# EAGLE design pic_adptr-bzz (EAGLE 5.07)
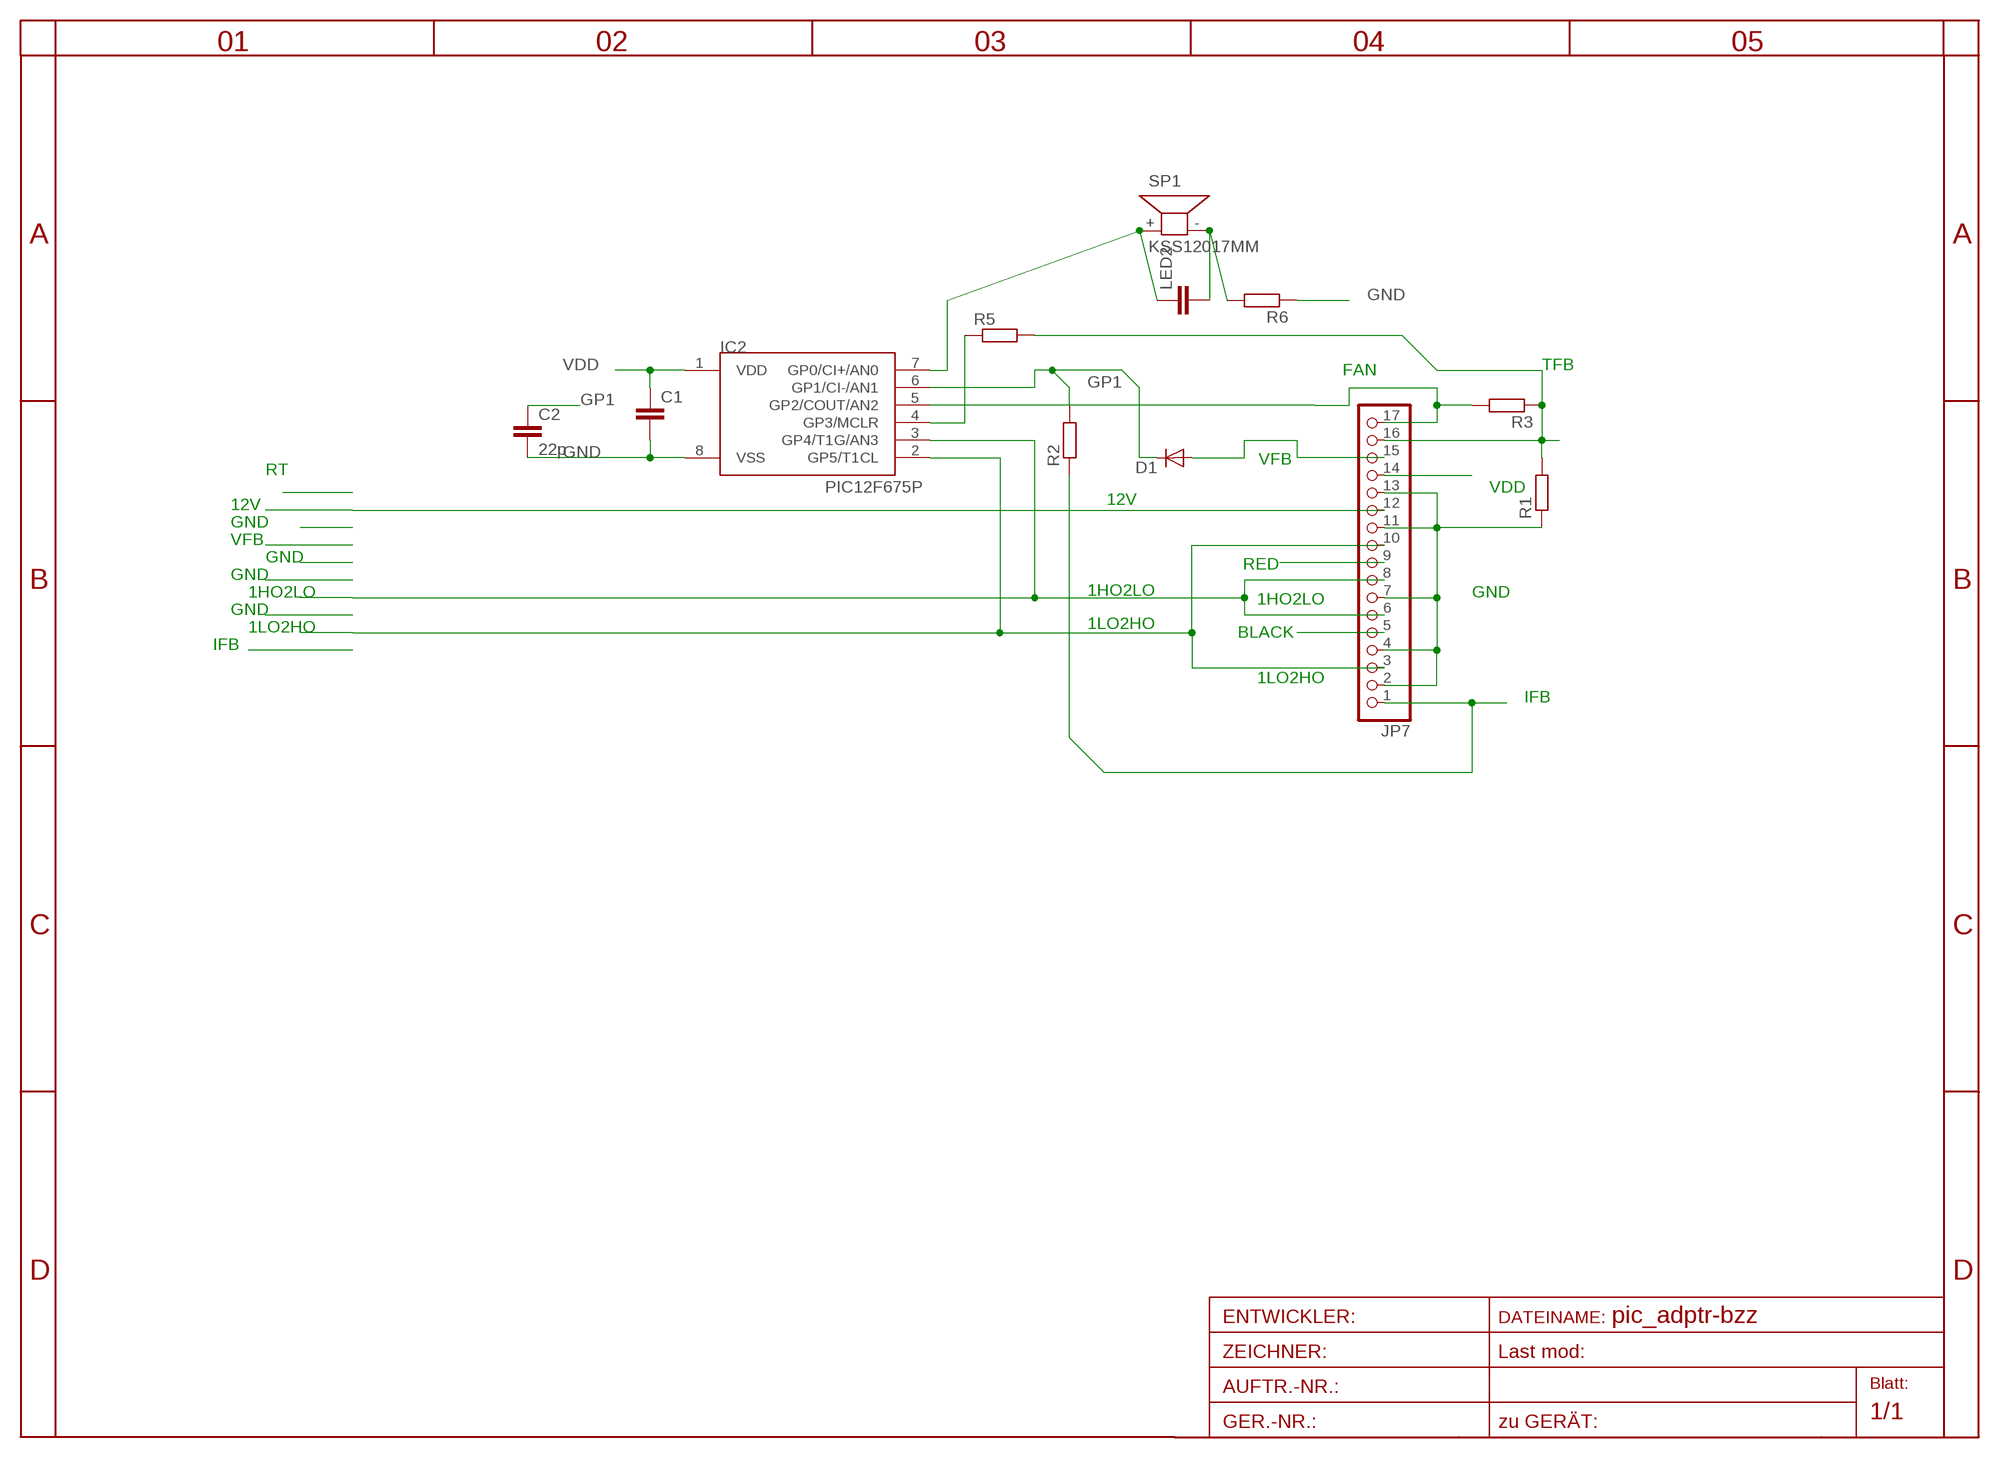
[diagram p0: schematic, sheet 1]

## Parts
C1  C-EUC1206  [C1206]
C2  22p  C-EUC0805  [C0805]
D1  DIODE-MINIMELF  [MINIMELF]
IC2  PIC12F675P  [DIL8]
JP7  PINHD-1X17  [1X17]
LED2  C-EUC1206K  [C1206K]
R1  R-EU_R1206  [R1206]
R2  R-EU_R0805  [R0805]
R3  R-EU_R0805  [R0805]
R5  R-EU_R0805  [R0805]
R6  R-EU_R0805  [R0805]
SP1  KSS12017MM  [KSS1202]

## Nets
1HO2LO: IC2.3(GP4/T1G/AN3) JP7.6 JP7.8
1LO2HO: IC2.2(GP5/T1CL) JP7.3 JP7.10
12V: JP7.12
BLACK: JP7.5
FAN: IC2.5(GP2/COUT/AN2) JP7.17 R3.2
GND: C1.2 C2.2 IC2.8(VSS) JP7.2 JP7.4 JP7.7 JP7.11 JP7.13 R1.1 R6.1
GP1: C2.1 D1.C IC2.6(GP1/CI-/AN1) R2.2
IFB: JP7.1 R2.1
N$3: IC2.4(GP3/MCLR) R5.1
N$4: IC2.7(GP0/CI+/AN0) LED2.1 SP1.+
N$5: LED2.2 R6.2 SP1.-
RED: JP7.9
TFB: JP7.16 R1.2 R3.1 R5.2
VDD: C1.1 IC2.1(VDD) JP7.14
VFB: D1.A JP7.15

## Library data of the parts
C1 C2 = rcl:C-EU: CAPACITOR, European symbol
D1 = diode:DIODE-: DIODE
IC2 = microchip-5:PIC12F6*: uPC nW 1k Program Flash memory 2x Timer Comparator 10b A/D converter/ 4xIN
JP7 = pinhead:PINHD-1X17: PIN HEADER
LED2 = rcl-2:C-EU: CAPACITOR, European symbol
R1-R3 R5 R6 = rcl:R-EU_: RESISTOR, European symbol
SP1 = buzzer:KSS1201: SPEAKER

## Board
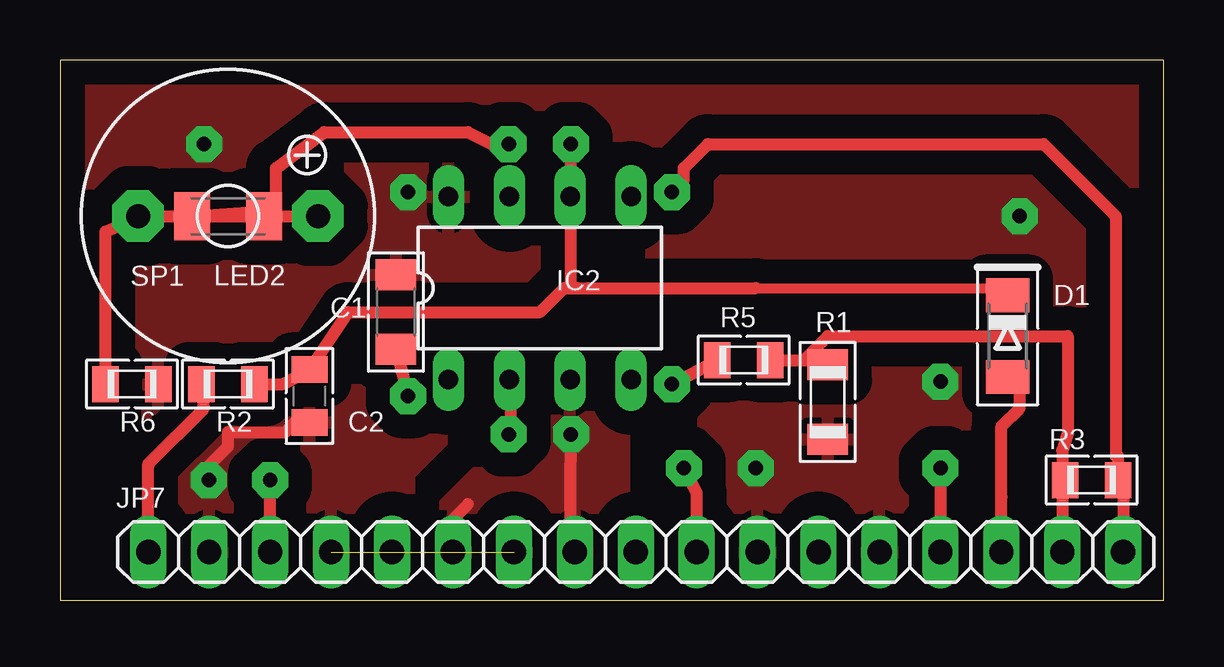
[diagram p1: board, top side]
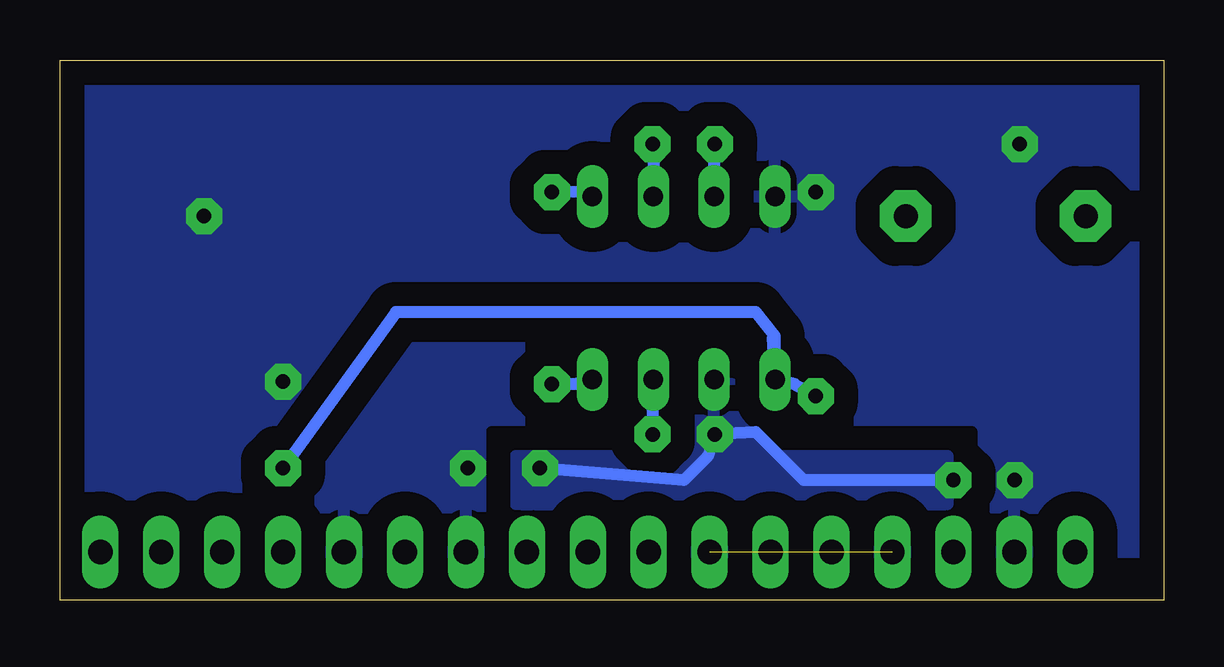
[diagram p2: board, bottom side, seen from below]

Size 46 x 22.5 mm. Coordinates in mm from the lower left corner, seen from the top.
Outline: 0,0 46,0 46,22.5 0,22.5 0,0
Copper layers (1*16): Top 0.035mm / dielectric 1.5mm / Bottom 0.035mm
Design rules "default *": minimum track width 10mil, minimum drill 20mil, track to track 8mil, track to pad 8mil, pad to pad 8mil, via to via 8mil, smd to smd 8mil, copper to edge 40mil, drill to drill 8mil, minimum pad ring 10mil, minimum via ring 8mil, stop-mask expansion 4mil, vias tented up to drill 0mil, thermal gap 10mil

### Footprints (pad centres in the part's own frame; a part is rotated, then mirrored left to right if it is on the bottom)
C1206 = smd 1.3 x 1.7: 1 -1.55,0; 2 1.55,0
C0805 = smd 1.1 x 1.5: 1 -1.1,0; 2 1.1,0
MINIMELF = smd 1.4 x 1.8: A 1.7,0; C -1.7,0
DIL8 = drill 0.8 long: 1 -3.81,-3.81; 2 -1.27,-3.81; 3 1.27,-3.81; 4 3.81,-3.81; 5 3.81,3.81; 6 1.27,3.81; 7 -1.27,3.81; 8 -3.81,3.81
1X17 = drill 1.016 long: 1 -20.32,0; 2 -17.78,0; 3 -15.24,0; 4 -12.7,0; 5 -10.16,0; 6 -7.62,0; 7 -5.08,0; 8 -2.54,0; 9 0,0; 10 2.54,0; 11 5.08,0; 12 7.62,0; 13 10.16,0; 14 12.7,0; 15 15.24,0; 16 17.78,0; 17 20.32,0
C1206K = smd 1.5 x 2: 1 -1.5,0; 2 1.5,0
R1206 = smd 1.3 x 1.7: 1 -1.55,0; 2 1.55,0
R0805 = smd 1.1 x 1.5: 1 -1.1,0; 2 1.1,0
KSS1202 = drill 1 pad 2.159 octagon: + 3.75,0; - -3.75,0

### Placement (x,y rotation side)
C1  14,12 90 top
C2  10.4,8.5 270 top
D1  39.5,11 270 top
IC2  20,13 0 top
JP7  24,2 0 top
LED2  7,16 0 top
R1  32,8.25 90 top
R2  7,9 0 top
R3  43,5 0 top
R5  28.5,10 0 top
R6  3,9 180 top
SP1  7,16 0 top

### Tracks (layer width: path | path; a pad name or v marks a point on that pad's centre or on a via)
1HO2LO  (via drill 0.6 pad 1.5)
  Top 0.5: v21.3,6.9 21.27,2.19 JP7.8 | 17,4 16,3 16,2.38 JP7.6
  Bottom 0.5: v21.3,6.9 IC2.3
  pour Top (isolate 1, rank 2): 20,8 23.5,8 23.5,1 21,1 21,3 18,3 18,2 17,1 15,1 15,3
1LO2HO  (via drill 0.6 pad 1.5)
  Top 0.5: JP7.3 v8.76,5 | JP7.10 26.54,4.46 v26,5.5 | v18.7,6.9 18.8,7.6 18.8,9.1
  Bottom 0.5: v8.76,5 9,5 15,5 16,6 17,7 v18.7,6.9 19,6 20,5 v26,5.5 | IC2.2 19,8.92 IC2.2
  pour Bottom (isolate 1): 19,9 20,8 20,7 21,6 27,6 27,4 9,4 9,6 16,6 17,7 17,8 18,9
FAN  (via drill 0.6 pad 1.5)
  Top 0.5: JP7.17 44.32,4.78 R3.2 44.1,6 44,6 44,16 41,19 27,19 26,18 26,17.5 v25.5,17
  Bottom 0.5: IC2.5 24.31,17.01 v25.5,17
GND  (via drill 0.6 pad 1.5)  (1 unrouted)
  Top 0.5: C2.2 9.8,7.4 9.4,7 7,7 7,6.4 6.2,5.6 v6.2,5
  other vias: 40,16 14.5,17 6,19 29,5.5 36.7,9.1
  pour Top (isolate 1, rank 3): 47,23 1,23 1,1 47,1
  pour Bottom (isolate 1, rank 3): 47,24 1,24 1,2 47,2
GP1  (via drill 0.6 pad 1.5)
  Top 0.406: D1.C 39,12.7 39,13 29,13
  Top 0.5: 21,13 20,12 12,12 C2.1 9.3,9 R2.2 | 21,13 21.3,13 | v21.3,19 21.3,16.3 21.3,14.7 21.3,13 | 29,13 22,13 21.59,13 21.3,13 | 21,13 21.3,13
  Bottom 0.5: IC2.6 21.27,18.77 v21.3,19
IFB
  Top 0.5: JP7.1 3.68,5.58 3.68,5.68 6,8 R2.1
N$3  (via drill 0.6 pad 1.5)
  Top 0.5: v25.5,9 R5.1
  Bottom 0.5: v25.5,9 24.52,9 IC2.4
N$4  (via drill 0.6 pad 1.5)
  Top 0.5: v18.7,19 18.2,18.8 18,19 17,19.5 11,19.5 9,18 9,16.25 LED2.1 SP1.+
  Bottom 0.5: IC2.7 18.73,18.77 v18.7,19
N$5
  Top 0.5: LED2.2 SP1.- 1.9,15.35 R6.2
TFB
  Top 0.5: 41.78,4.88 JP7.16 | 41.78,4.88 R3.1 | 41.78,4.88 41.78,6.22 42,7 42,11 32,11 31,10 | 31,10 31.8,10 R1.2 | R5.2 31,10
VDD  (via drill 0.6 pad 1.5)
  Top 0.5: v36.7,5.5 JP7.14 | C1.1 v14.5,8.5
  Bottom 0.5: v36.7,5.5 32,12 17,12 16.2,11 16.2,9.48 IC2.1 | IC2.1 16.28,11 | v14.5,8.5 15.38,9 IC2.1
VFB
  Top 0.5: JP7.15 39.24,4.29 39.24,7.24 40,8 40,8.8 D1.A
